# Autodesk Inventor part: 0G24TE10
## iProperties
Created: 2007-01
Description: 2000x1000x10
Document SubType Name: Blech
Designer: R.Pilz
Part Number: 0G24TE10
ArtNrPrefix: HZ
ArtNrAuto: 0
EDVNum=ArtNr: 0
Bez=Mat: 0
ArtNrBackSpace: 0
EDVNrBackSpace: 0
EDVNrAuto: 0
ProdGruppe: ÜKWW
ProdBezeichnung: Blende
ArtNr: HZG24TE10
EDVNr: L1234
KommaZuschnitt: 0
Zeichnungsnummer: 0G24 TE ST
Konstrukteur: R.Pilz
Erstellungsdatum: 10.01.2007
GesGewicht: 0,6kg
Material: Standard
Title: Platte
Author: R.Pilz
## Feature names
1. Abgeleiteter Körper1 [Tagging]
